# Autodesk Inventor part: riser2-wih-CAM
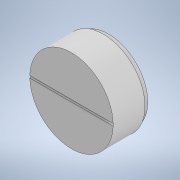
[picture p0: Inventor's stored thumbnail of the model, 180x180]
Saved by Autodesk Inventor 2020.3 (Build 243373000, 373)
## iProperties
Created: 2020-06
Part Number: riser2-wih-CAM
Material: Generic
Document SubType Name: Modeling
Designer: e
Density: 1 g/cm^3
Appearance: Default
Author: e
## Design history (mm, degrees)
derived "fixture-well.ipt"
  workaxis "Work Axis1"
  workaxis "Work Axis2"
  workaxis "Work Axis3"
  workaxis "Work Axis4"
  workaxis "Work Axis5"
  workaxis "Work Axis6"
  workaxis "Work Axis7"
  workaxis "Work Axis8"
  workaxis "Work Axis9"
  workaxis "Work Axis10"
  workaxis "Work Axis11"
  workaxis "Work Axis12"
  workaxis "Work Axis13"
  workaxis "Work Axis14"
  workaxis "Work Axis15"
  workaxis "Work Axis16"
  workaxis "Work Axis17"
  workaxis "Work Axis18"
  workaxis "Work Axis19"
  workaxis "Work Axis20"
  workaxis "Work Axis21"
  workaxis "Work Axis22"
  workaxis "Work Axis23"
  workaxis "Work Axis24"
  workaxis "Work Axis25"
  workaxis "Work Axis26"
  workaxis "Work Axis27"
  workaxis "Work Axis28"
  workaxis "Work Axis29"
  workaxis "Work Axis30"
  workaxis "Work Axis31"
  workaxis "Work Axis32"
  workaxis "Work Axis33"
  workaxis "Work Axis34"
  workaxis "Work Axis35"
  workaxis "Work Axis36"
  workaxis "Work Axis37"
  workaxis "Work Axis38"
  workaxis "Work Axis39"
  workaxis "Work Axis40"
  workaxis "Work Axis41"
  workaxis "Work Axis42"
  workaxis "Work Axis43"
  workaxis "Work Axis44"
  workaxis "Work Axis45"
  workaxis "Work Axis46"
  workaxis "Work Axis47"
  workaxis "Work Axis48"
  workaxis "Work Axis49"
  workaxis "Work Axis50"
  workaxis "Work Axis51"
  workaxis "Work Axis52"
  workaxis "Work Axis53"
  workaxis "Work Axis54"
  workaxis "Work Axis55"
  workaxis "Work Axis56"
  workaxis "Work Axis57"
  workaxis "Work Axis58"
  workaxis "Work Axis59"
  workaxis "Work Axis60"
  workaxis "Work Axis61"
  workaxis "Work Axis62"
  workaxis "Work Axis63"
  workaxis "Work Axis64"
  workaxis "Work Axis65"
  workaxis "Work Axis66"
  workaxis "Work Axis67"
  workaxis "Work Axis68"
  workaxis "Work Axis69"
  workaxis "Work Axis70"
  workaxis "Work Axis71"
  workaxis "Work Axis72"
  workaxis "Work Axis73"
  workaxis "Work Axis74"
  workaxis "Work Axis75"
  workaxis "Work Axis76"
  workaxis "Work Axis77"
  workaxis "Work Axis78"
  workaxis "Work Axis79"
  workaxis "Work Axis80"
  workaxis "Work Axis81"
  workaxis "Work Axis82"
  workaxis "Work Axis83"
  workaxis "Work Axis84"
  workaxis "Work Axis85"
  workaxis "Work Axis86"
  workaxis "Work Axis87"
  workaxis "Work Axis88"
  workaxis "Work Axis89"
  workaxis "Work Axis90"
  workaxis "Work Axis91"
  workaxis "Work Axis92"
  workaxis "Work Axis93"
  workaxis "Work Axis94"
  workaxis "Work Axis95"
  workaxis "Work Axis96"
  workaxis "Work Axis97"
  workaxis "Work Axis98"
  workaxis "Work Axis99"
  workaxis "Work Axis100"
  workaxis "Work Axis101"
  workaxis "Work Axis102"
  workaxis "Work Axis103"
  workaxis "Work Axis104"
  workaxis "Work Axis105"
  workaxis "Work Axis106"
  workaxis "Work Axis107"
  workaxis "Work Axis108"
  workaxis "Work Axis109"
  workaxis "Work Axis110"
  workaxis "Work Axis111"
  workaxis "Work Axis112"
  workaxis "Work Axis113"
  workaxis "Work Axis114"
  workaxis "Work Axis115"
  workaxis "Work Axis116"
  workaxis "Work Axis117"
  workaxis "Work Axis118"
  workaxis "Work Axis119"
  workaxis "Work Axis120"
  workaxis "Work Axis121"
  workaxis "Work Axis122"
  workaxis "Work Axis123"
  workaxis "Work Axis124"
  workaxis "Work Axis125"
  workaxis "Work Axis126"
  workaxis "Work Axis127"
  workaxis "Work Axis128"
  workaxis "Work Axis129"
  workaxis "Work Axis130"
  workaxis "Work Axis131"
  workaxis "Work Axis132"
  workaxis "Work Axis133"
  workaxis "Work Axis134"
  workaxis "Work Axis135"
  workaxis "Work Axis136"
  workaxis "Work Axis137"
  workaxis "Work Axis138"
  workaxis "Work Axis139"
  workaxis "Work Axis140"
  workaxis "Work Axis141"
  workaxis "Work Axis142"
  workaxis "Work Axis143"
  workaxis "Work Axis144"
  workaxis "Work Axis145"
  workaxis "Work Axis146"
  workaxis "Work Axis147"
  workaxis "Work Axis148"
  workaxis "Work Axis149"
  workaxis "Work Axis150"
  workaxis "Work Axis151"
  workaxis "Work Axis152"
  workaxis "Work Axis153"
  workaxis "Work Axis154"
  workaxis "Work Axis155"
  workaxis "Work Axis156"
  workaxis "Work Axis157"
  workaxis "Work Axis158"
  workaxis "Work Axis159"
  workaxis "Work Axis160"
  workaxis "Work Axis161"
  workaxis "Work Axis162"
  workaxis "Work Axis163"
  workaxis "Work Axis164"
  workaxis "Work Axis165"
  workaxis "Work Axis166"
  workaxis "Work Axis167"
  workaxis "Work Axis168"
  workaxis "Work Axis169"
  workaxis "Work Axis170"
  workaxis "Work Axis171"
  workaxis "Work Axis172"
  workaxis "Work Axis173"
  workaxis "Work Axis174"
  workaxis "Work Axis175"
  workaxis "Work Axis176"
  workaxis "Work Axis177"
  workaxis "Work Axis178"
  workaxis "Work Axis179"
  workaxis "Work Axis180"
  workaxis "Work Axis181"
  workaxis "Work Axis182"
  workaxis "Work Axis183"
  workaxis "Work Axis184"
  workaxis "Work Axis185"
  workaxis "Work Axis186"
  workaxis "Work Axis187"
  workaxis "Work Axis188"
  workaxis "Work Axis189"
  workaxis "Work Axis190"
  workaxis "Work Axis191"
  workaxis "Work Axis192"
  workaxis "Work Axis193"
  workaxis "Work Axis194"
  workaxis "Work Axis195"
  workaxis "Work Axis196"
  workaxis "Work Axis197"
  workaxis "Work Axis198"
  workaxis "Work Axis199"
  workaxis "Work Axis200"
  workaxis "Work Axis201"
  workaxis "Work Axis202"
  workaxis "Work Axis203"
  workaxis "Work Axis204"
  workaxis "Work Axis205"
  workaxis "Work Axis206"
  workaxis "Work Axis207"
  workaxis "Work Axis208"
  workaxis "Work Axis209"
  workaxis "Work Axis210"
  workaxis "Work Axis211"
  workaxis "Work Axis212"
  workaxis "Work Axis213"
  workaxis "Work Axis214"
  workaxis "Work Axis215"
  workaxis "Work Axis216"
  workaxis "Work Axis217"
  workaxis "Work Axis218"
  workaxis "Work Axis219"
  workaxis "Work Axis220"
  workaxis "Work Axis221"
  workaxis "Work Axis222"
  workaxis "Work Axis223"
  workaxis "Work Axis224"
  workaxis "Work Axis225"
  workaxis "Work Axis226"
  workaxis "Work Axis227"
  workaxis "Work Axis228"
  workaxis "Work Axis229"
  workaxis "Work Axis230"
  workaxis "Work Axis231"
  workaxis "Work Axis232"
  workaxis "Work Axis233"
  workaxis "Work Axis234"
  workaxis "Work Axis235"
  workaxis "Work Axis236"
  workaxis "Work Axis237"
  workaxis "Work Axis238"
  workaxis "Work Axis239"
sketch "Sketch1"
  geometry: C1 r 47.75 at (0, 0) reference; 1 further point
extrude "riser" new body sketch "Sketch1" taper "d2" = 0 deg; distance "riser_height" = 42.5
combine "Combine1"
  body "Solid1"
workaxis "Work Axis241"
sketch "Sketch2"
  geometry: L1 (66.852, 0)-(-66.85, 0) reference; L2 (44.371, 7.5)-(44.371, -7.5); L3 (44.371, -7.5)-(47.75, -7.5); L4 (47.75, -7.5)-(47.75, 7.5); L5 (47.75, 7.5)-(44.371, 7.5); C1 r 47.75 at (0, 0) reference; A1 r 45 centre (0, 0) between (44.371, 7.5) and (44.371, -7.5) reference; 1 further point
  constraints: 8 end point, 2 perpendicular, 2 point on circle, 1 horizontal, 1 tangent, 1 other
  dimensions: "flat_width" = 15 distance of L2.start L2.end
extrude "Extrusion2" cut sketch "Sketch2" stored distance "d4" = 10; taper "d5" = 0 deg
workplane "Work Plane2"
sketch "Sketch4"
  geometry: L1 (47.75, 42.5)-(-47.75, 42.5) reference; L2 (0, -13.648)-(0, 51.858) reference; L3 (-1.25, 42.5)-(0, 41.25); L4 (1.25, 42.5)-(0, 41.25); 1 further point
  constraints: 4 end point, 3 point on line, 1 perpendicular
  dimensions: "d37" = 90 deg angle of L4 L3; "vee_width" = 2.5 distance of L4.start L3.start
thicken "Thicken1" dims "d13" = 0.025, "base_clearance" = 0.03
extrude "vee" cut sketch "Sketch4" extent not by distance; stored distance "d41" = 0; taper "d42" = 0 deg
sketch "Sketch6"
  geometry: L1 (0, 0)-(-39.7, 0); C1 r 2.35 at (-39.7, 0) reference; C2 r 47.75 at (0, 0) reference; A1 r 44.97 centre (0, 0) between (44.341, 7.497) and (44.341, -7.497) reference; 3 further points
  constraints: 2 end point, 1 horizontal, 1 symmetric about line
  dimensions: "d29" = 80 distance of point (0, -40) point (0, 40)
hole "Hole2" sketch "Sketch6" at (0, 40), (0, -40) diameter "d30" = 3; stored, may be unused: countersink angle "d34" = 90 deg, drill point angle "d36" = 118 deg; dims "d31" = 6, "d32" = 4, "d33" = 2, "d35" = 6.5
chamfer "Chamfer1" distance "d14" = 0.5; stored, may be unused: second distance "d15" = 2, angle "d16" = 45 deg
feature "Solid1::fixture-well.ipt"
tag "TaggingFeature1"
body "Solid2"
